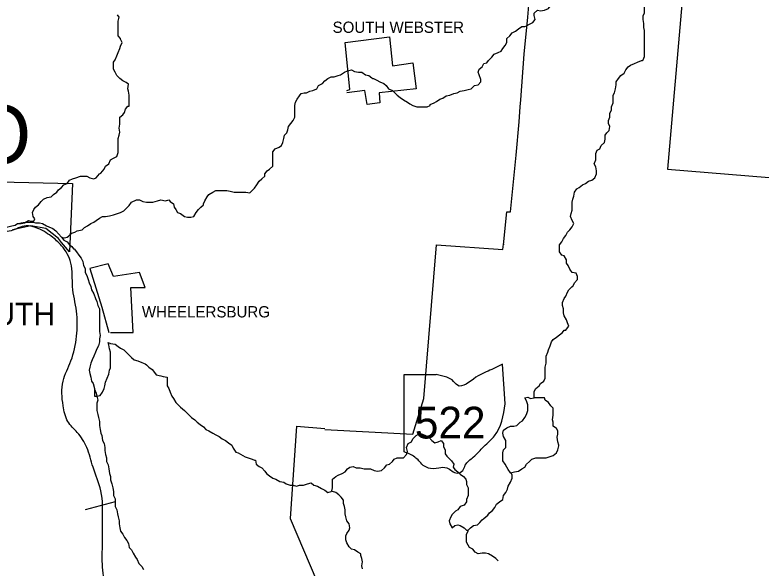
# Model space of a CAD drawing. Extents: x 0 to 34, y 0 to 22.
# Drawn here: x 6.387 to 7.678, y 15.869 to 16.826 of the extents above; entities that cross this region are included whole.
import ezdxf

# ---------------------------------------------------------------- set-up
doc = ezdxf.new("R2010")
doc.units = 0
doc.layers.add('Default', color=7, linetype='Continuous')
doc.layers.add('TR_Turning_Path1', color=7, linetype='Continuous')

msp = doc.modelspace()

# ---------------------------------------------------------------- linework, layer by layer
at = {"layer": 'Default'}
msp.add_line((7.0753, 16.1005), (7.0753, 16.1005), dxfattribs=at)
for points in [[(7.232, 16.4277), (7.2375, 16.485), (7.2443, 16.485), (7.2539, 16.5832), (7.2593, 16.6404), (7.2607, 16.6663), (7.262, 16.6786), (7.2675, 16.7577), (7.2743, 16.8218), (7.2784, 16.8777), (7.2784, 16.8777), (7.2784, 16.8777)], [(7.2716, 16.8068), (7.277, 16.8095), (7.2825, 16.8122), (7.2866, 16.8177), (7.2852, 16.8245), (7.2852, 16.8286), (7.2907, 16.834), (7.2961, 16.8327), (7.3029, 16.834), (7.3098, 16.8368), (7.3125, 16.8409), (7.3179, 16.8422), (7.3261, 16.845), (7.3316, 16.8463), (7.337, 16.8504), (7.337, 16.8572), (7.3425, 16.8613), (7.3438, 16.8681), (7.3452, 16.8695), (7.3452, 16.8709)], [(7.4734, 16.7481), (7.4761, 16.7536), (7.4761, 16.7604), (7.4761, 16.7672), (7.4761, 16.7727), (7.4761, 16.7795), (7.4761, 16.785), (7.4761, 16.7918), (7.4761, 16.7986), (7.4747, 16.804), (7.4747, 16.8109), (7.4734, 16.8177), (7.4734, 16.8245), (7.4761, 16.8286), (7.4761, 16.8368), (7.4761, 16.8422), (7.4734, 16.8463), (7.4706, 16.8531), (7.4679, 16.8586), (7.4652, 16.8613), (7.4638, 16.8613)], [(7.5415, 16.8572), (7.5156, 16.5586), (7.8674, 16.53), (7.8579, 16.3964), (7.926, 16.3909), (7.9124, 16.2178), (7.9056, 16.1223), (8.2369, 16.1019), (8.2751, 16.0978), (8.3241, 16.0951)], [(6.5694, 16.785), (6.5653, 16.7891), (6.5653, 16.7959), (6.5653, 16.8013), (6.5653, 16.8095), (6.5653, 16.815), (6.5667, 16.8218), (6.564, 16.8259)], [(7.2034, 16.7427), (7.2061, 16.7468), (7.2116, 16.7522), (7.2157, 16.7577), (7.2225, 16.7604), (7.228, 16.7631), (7.2307, 16.7672), (7.2348, 16.7727), (7.2375, 16.7781), (7.2375, 16.785), (7.243, 16.7891), (7.247, 16.7945), (7.2525, 16.7972), (7.258, 16.8013), (7.2634, 16.8054), (7.2689, 16.8054), (7.2716, 16.8068)], [(6.5844, 16.6677), (6.5844, 16.6745), (6.5844, 16.68), (6.5844, 16.6868), (6.5831, 16.6936), (6.5817, 16.6977), (6.5831, 16.7059), (6.579, 16.7086), (6.5735, 16.7113), (6.5681, 16.7154), (6.5626, 16.7209), (6.5599, 16.7263), (6.5572, 16.7318), (6.5572, 16.7372), (6.5572, 16.7441), (6.5599, 16.7481), (6.5626, 16.755), (6.5653, 16.7604), (6.5681, 16.7672), (6.5694, 16.7713), (6.5722, 16.7781), (6.5694, 16.7836), (6.5694, 16.785)], [(6.9607, 16.695), (6.9662, 16.6963), (6.958, 16.7781), (7.0344, 16.7877), (7.0398, 16.7372), (7.0753, 16.7427), (7.0807, 16.6977), (7.0166, 16.6909), (7.018, 16.6732), (6.9962, 16.6704), (6.9921, 16.695), (6.9607, 16.6909)], [(7.3984, 16.5941), (7.4011, 16.5995), (7.4066, 16.605), (7.4079, 16.6104), (7.4079, 16.6173), (7.4107, 16.6214), (7.4147, 16.6254), (7.4161, 16.6323), (7.4134, 16.6377), (7.4134, 16.6432), (7.4161, 16.6486), (7.4161, 16.6554), (7.4188, 16.6609), (7.4188, 16.6663), (7.4216, 16.6732), (7.4216, 16.68), (7.4216, 16.6868), (7.4243, 16.6909), (7.4257, 16.6977), (7.427, 16.7045), (7.427, 16.71), (7.4311, 16.7154), (7.4352, 16.7209), (7.4407, 16.725), (7.4434, 16.7304), (7.4475, 16.7359), (7.4516, 16.7386), (7.4584, 16.7413), (7.4638, 16.7441), (7.4706, 16.7468), (7.472, 16.7468), (7.4734, 16.7481)], [(7.1053, 16.6704), (7.1121, 16.6732), (7.1162, 16.6759), (7.1216, 16.68), (7.1271, 16.6813), (7.1325, 16.6854), (7.1393, 16.6868), (7.1462, 16.6895), (7.1516, 16.6909), (7.1571, 16.6936), (7.1639, 16.695), (7.1707, 16.6963), (7.1761, 16.6977), (7.1816, 16.7032), (7.1884, 16.7045), (7.1925, 16.71), (7.1925, 16.7141), (7.1898, 16.7222), (7.1884, 16.7263), (7.1898, 16.7318), (7.1952, 16.7359), (7.198, 16.7413), (7.2034, 16.7427)], [(6.8912, 16.6909), (6.8966, 16.6936), (6.9021, 16.695), (6.9089, 16.6977), (6.9116, 16.7032), (6.9185, 16.7072), (6.9226, 16.7113), (6.928, 16.7154), (6.9335, 16.7182), (6.9389, 16.7182), (6.9457, 16.7209), (6.9498, 16.7222), (6.9566, 16.7263), (6.9621, 16.7291), (6.9689, 16.7304), (6.9744, 16.7277), (6.9812, 16.7263), (6.9866, 16.7263), (6.9934, 16.7222), (6.9989, 16.7209), (7.0044, 16.7168), (7.0057, 16.7154), (7.0071, 16.7154)], [(7.0071, 16.7154), (7.0125, 16.7127), (7.018, 16.71), (7.0248, 16.7072), (7.0289, 16.7032), (7.033, 16.6977), (7.0398, 16.695), (7.0439, 16.6909), (7.048, 16.6868), (7.0534, 16.6827), (7.0589, 16.6786), (7.0657, 16.6745), (7.0698, 16.6718), (7.0753, 16.6691), (7.0821, 16.6663), (7.0889, 16.6663), (7.0943, 16.6663), (7.0998, 16.6663), (7.1053, 16.6691), (7.1053, 16.6704)], [(6.8189, 16.5505), (6.823, 16.5559), (6.8271, 16.5586), (6.8326, 16.5641), (6.8326, 16.5709), (6.8326, 16.5764), (6.8326, 16.5832), (6.8326, 16.5886), (6.8367, 16.5941), (6.8435, 16.5968), (6.8476, 16.5995), (6.8503, 16.605), (6.8517, 16.6118), (6.853, 16.6173), (6.8571, 16.6214), (6.8585, 16.6268), (6.8598, 16.6323), (6.8639, 16.6377), (6.868, 16.6432), (6.8707, 16.6486), (6.8707, 16.6568), (6.8707, 16.6623), (6.8707, 16.6691), (6.8721, 16.6745), (6.8748, 16.68), (6.8789, 16.6854), (6.8816, 16.6895), (6.8871, 16.6909), (6.8912, 16.6909)], [(6.5272, 16.5436), (6.5326, 16.5505), (6.5353, 16.5518), (6.5408, 16.5586), (6.5435, 16.5641), (6.549, 16.5682), (6.5517, 16.575), (6.5572, 16.5777), (6.5626, 16.5804), (6.5653, 16.5873), (6.5653, 16.5927), (6.5653, 16.5995), (6.5653, 16.605), (6.5653, 16.6118), (6.5667, 16.6173), (6.5681, 16.6227), (6.5667, 16.6295), (6.5681, 16.6363), (6.5681, 16.6418), (6.5681, 16.6486), (6.5735, 16.6527), (6.5762, 16.6568), (6.5776, 16.6623), (6.5817, 16.6677), (6.5844, 16.6677), (6.5844, 16.6677)], [(7.3466, 16.4537), (7.3507, 16.4591), (7.3534, 16.4646), (7.3507, 16.47), (7.3479, 16.4768), (7.3493, 16.4823), (7.3507, 16.4877), (7.3507, 16.4932), (7.3507, 16.5014), (7.352, 16.5068), (7.3534, 16.5123), (7.3548, 16.5191), (7.3588, 16.5245), (7.3629, 16.5273), (7.3684, 16.5314), (7.3738, 16.5341), (7.3793, 16.5382), (7.3848, 16.5395), (7.3902, 16.5436), (7.3929, 16.5505), (7.3929, 16.5559), (7.3916, 16.5627), (7.3888, 16.5682), (7.3916, 16.575), (7.3916, 16.5804), (7.3916, 16.5859), (7.3943, 16.5914), (7.3984, 16.5941)], [(6.2327, 16.5395), (6.4863, 16.5341), (6.4808, 16.4155), (6.4672, 16.4318), (6.4617, 16.4387), (6.4399, 16.4564), (6.414, 16.4605), (6.3826, 16.4537)], [(6.4194, 16.4686), (6.4208, 16.4727), (6.4181, 16.4768), (6.4167, 16.4836), (6.4194, 16.4891), (6.4222, 16.4932), (6.4276, 16.4973), (6.4317, 16.5027), (6.4358, 16.5068), (6.4426, 16.5096), (6.4494, 16.5109), (6.4535, 16.515), (6.459, 16.5191), (6.4617, 16.5232), (6.4672, 16.5273), (6.4713, 16.5314), (6.4767, 16.5341), (6.4808, 16.5395), (6.4863, 16.5423), (6.4917, 16.5436), (6.4999, 16.5464), (6.5053, 16.5464), (6.5108, 16.5464), (6.5163, 16.5436), (6.5231, 16.5423), (6.5272, 16.5436), (6.5272, 16.5436)], [(6.7126, 16.4986), (6.7153, 16.5041), (6.7194, 16.5109), (6.7221, 16.515), (6.7289, 16.5191), (6.7344, 16.5218), (6.7399, 16.5218), (6.7467, 16.5218), (6.7535, 16.5218), (6.7589, 16.5205), (6.7658, 16.5191), (6.7726, 16.5191), (6.7808, 16.5191), (6.7862, 16.5191), (6.793, 16.5177), (6.7971, 16.5218), (6.8012, 16.5259), (6.8053, 16.5314), (6.8094, 16.5382), (6.8135, 16.5423), (6.8189, 16.5464), (6.8189, 16.5491), (6.8189, 16.5505)], [(6.4794, 16.4427), (6.4849, 16.4482), (6.4903, 16.4496), (6.4944, 16.4523), (6.5026, 16.4537), (6.5067, 16.4577), (6.5122, 16.4605), (6.5176, 16.4646), (6.5231, 16.4673), (6.5272, 16.47), (6.5326, 16.4741), (6.5381, 16.4768), (6.5435, 16.4768), (6.5503, 16.4782), (6.5572, 16.4796), (6.564, 16.4823), (6.5694, 16.4836), (6.5749, 16.4864), (6.579, 16.4905), (6.5844, 16.4959), (6.5885, 16.5014), (6.5967, 16.5055), (6.5967, 16.5055)], [(6.5967, 16.5055), (6.6021, 16.5055), (6.6076, 16.5027), (6.6144, 16.5014), (6.6199, 16.5014), (6.6253, 16.5014), (6.6335, 16.5041), (6.639, 16.5055), (6.6471, 16.5041), (6.6526, 16.5055), (6.6553, 16.5027), (6.6608, 16.4986), (6.6621, 16.4932), (6.6649, 16.4891), (6.6676, 16.4836), (6.673, 16.4823), (6.6799, 16.4768), (6.6853, 16.4755), (6.6908, 16.4755), (6.6962, 16.4768), (6.7003, 16.4836), (6.7044, 16.4891), (6.7085, 16.4932), (6.7126, 16.4973), (6.7126, 16.4973), (6.7126, 16.4986)], [(6.3036, 16.4523), (6.309, 16.4523), (6.3158, 16.4523), (6.3226, 16.4537), (6.3295, 16.4537), (6.3363, 16.4537), (6.3417, 16.4564), (6.3472, 16.4564), (6.3554, 16.4577), (6.3608, 16.4577), (6.3676, 16.4577), (6.3745, 16.4591), (6.3813, 16.4605), (6.3867, 16.4618), (6.3908, 16.4646), (6.3922, 16.4646)], [(6.3922, 16.4646), (6.3976, 16.4646), (6.4031, 16.4659), (6.4099, 16.47), (6.4154, 16.4686), (6.4194, 16.4686)], [(6.3922, 16.4646), (6.3976, 16.4659), (6.4045, 16.4673), (6.4099, 16.4673), (6.4181, 16.4673), (6.4222, 16.4659), (6.429, 16.4659), (6.4344, 16.4646), (6.4413, 16.4605), (6.4454, 16.4591), (6.4522, 16.4564), (6.4576, 16.4523), (6.4617, 16.4468), (6.4672, 16.4414), (6.4672, 16.4414)], [(7.352, 16.3555), (7.3548, 16.3623), (7.3602, 16.3678), (7.3602, 16.3732), (7.3575, 16.3787), (7.3507, 16.38), (7.3466, 16.3855), (7.3438, 16.3923), (7.3411, 16.3964), (7.3411, 16.4018), (7.337, 16.4087), (7.3329, 16.41), (7.3289, 16.4155), (7.3289, 16.4209), (7.3289, 16.4277), (7.3329, 16.4332), (7.3357, 16.4387), (7.3398, 16.4441), (7.3425, 16.4496), (7.3452, 16.4523), (7.3466, 16.4537)], [(6.4672, 16.4414), (6.4726, 16.44), (6.4767, 16.4414), (6.4794, 16.4427)], [(6.4672, 16.4414), (6.4713, 16.4359), (6.4767, 16.4332), (6.4808, 16.4277), (6.4849, 16.425), (6.4876, 16.4209), (6.489, 16.4209)], [(7.0943, 16.1619), (7.1162, 16.4277)], [(7.1162, 16.4277), (7.2307, 16.4196)], [(7.2307, 16.4196), (7.232, 16.4291), (7.232, 16.4277)], [(6.489, 16.4209), (6.4931, 16.4155), (6.4972, 16.41), (6.5013, 16.4046), (6.504, 16.3991), (6.5053, 16.3923), (6.5081, 16.3868), (6.5081, 16.38), (6.5108, 16.3746), (6.5135, 16.3678), (6.5149, 16.3623), (6.5176, 16.3555), (6.519, 16.35), (6.5231, 16.3432), (6.5258, 16.335)], [(6.5517, 16.2764), (6.5912, 16.2764), (6.5872, 16.3541), (6.6117, 16.3541), (6.6021, 16.38), (6.5572, 16.3732), (6.5476, 16.395), (6.5163, 16.3868), (6.5367, 16.32), (6.549, 16.2764)], [(7.3411, 16.2819), (7.3452, 16.2873), (7.3425, 16.2928), (7.3411, 16.2982), (7.337, 16.305), (7.3357, 16.3105), (7.3357, 16.3173), (7.3343, 16.3228), (7.3343, 16.3282), (7.337, 16.335), (7.3398, 16.3391), (7.3425, 16.3459), (7.3452, 16.35), (7.3507, 16.3555), (7.352, 16.3555)], [(6.5258, 16.335), (6.5285, 16.3296), (6.5299, 16.3228), (6.5326, 16.3173), (6.5326, 16.3105), (6.5326, 16.305), (6.5326, 16.2982), (6.5326, 16.2914), (6.5326, 16.2859), (6.5326, 16.2778), (6.534, 16.271), (6.5326, 16.2655), (6.5326, 16.26), (6.5313, 16.2532), (6.5285, 16.2478), (6.5258, 16.2423), (6.5231, 16.2355), (6.5203, 16.2287), (6.5176, 16.2232), (6.5163, 16.2164), (6.5149, 16.211), (6.5163, 16.2055), (6.5176, 16.1987), (6.519, 16.1919), (6.5217, 16.1878), (6.5244, 16.1796), (6.5244, 16.1796), (6.5244, 16.1782)], [(7.2852, 16.1632), (7.2852, 16.1701), (7.2852, 16.1741), (7.2879, 16.1796), (7.2934, 16.1837), (7.2961, 16.1878), (7.3016, 16.1919), (7.3043, 16.1973), (7.3043, 16.2041), (7.3043, 16.211), (7.3043, 16.2164), (7.3057, 16.2232), (7.3057, 16.2287), (7.3057, 16.2355), (7.3084, 16.2423), (7.3098, 16.2464), (7.3125, 16.2532), (7.3152, 16.26), (7.3179, 16.2641), (7.3234, 16.2682), (7.3289, 16.2723), (7.3343, 16.2764), (7.337, 16.2805), (7.3398, 16.2805), (7.3411, 16.2819)], [(6.5244, 16.1782), (6.5244, 16.1714), (6.5244, 16.166), (6.5285, 16.166), (6.534, 16.1673), (6.5381, 16.1728), (6.5408, 16.1796), (6.5422, 16.1837), (6.5435, 16.1905), (6.5462, 16.1973), (6.549, 16.2041), (6.5503, 16.211), (6.5517, 16.2151), (6.5517, 16.2219), (6.5517, 16.2287), (6.5517, 16.2355), (6.5517, 16.2423), (6.5503, 16.2478), (6.549, 16.2546), (6.5476, 16.2587)], [(6.5476, 16.2587), (6.5517, 16.2573), (6.5599, 16.256), (6.5653, 16.2519), (6.5694, 16.2491), (6.5749, 16.2464), (6.579, 16.2423), (6.5844, 16.2369), (6.5885, 16.2328), (6.5926, 16.2287), (6.5994, 16.2273), (6.6062, 16.2246), (6.6117, 16.2219), (6.6144, 16.2205)], [(6.6144, 16.2205), (6.6185, 16.2164), (6.624, 16.2123), (6.6281, 16.2069), (6.6308, 16.2028), (6.639, 16.2014), (6.6431, 16.2001), (6.6499, 16.1987), (6.6499, 16.1905), (6.6499, 16.1837), (6.6526, 16.1796), (6.6553, 16.1728), (6.658, 16.166), (6.6608, 16.1619), (6.6649, 16.1551), (6.669, 16.151), (6.673, 16.1469), (6.6799, 16.1414), (6.6826, 16.1387), (6.688, 16.1332), (6.6921, 16.1292), (6.6976, 16.1251), (6.6976, 16.1251)], [(7.2349, 16.1527), (7.2303, 16.2217)], [(7.0601, 16.0698), (7.0601, 16.2033), (7.1153, 16.2033)], [(6.5244, 16.1782), (6.5272, 16.1714), (6.5285, 16.166), (6.5299, 16.1592), (6.5285, 16.1537), (6.5285, 16.1469), (6.5285, 16.1414), (6.5299, 16.1346), (6.5313, 16.1292), (6.5326, 16.1223), (6.5326, 16.1155), (6.534, 16.1087), (6.5353, 16.1019), (6.5367, 16.0978), (6.5381, 16.0896), (6.5408, 16.0842), (6.5422, 16.0773), (6.5422, 16.0719), (6.5435, 16.0651), (6.5449, 16.0596), (6.5449, 16.0528), (6.5476, 16.0474), (6.549, 16.0405), (6.5503, 16.0324), (6.5517, 16.0269), (6.5517, 16.0214), (6.5544, 16.0146), (6.5558, 16.0078), (6.5572, 16.001), (6.5572, 15.9942), (6.5599, 15.9887), (6.5599, 15.9833), (6.5599, 15.9751), (6.5626, 15.9696), (6.564, 15.9628), (6.5653, 15.9574), (6.5667, 15.9505), (6.5667, 15.9451), (6.5681, 15.9383), (6.5694, 15.9328), (6.5735, 15.9274)], [(7.0753, 16.1005), (7.0943, 16.1619), (7.0943, 16.1619)], [(7.2443, 16.0337), (7.2402, 16.0392), (7.2375, 16.0433), (7.2348, 16.0487), (7.2307, 16.0542), (7.2307, 16.0596), (7.2307, 16.0678), (7.232, 16.0733), (7.2361, 16.0773), (7.2361, 16.0842), (7.2361, 16.0896), (7.232, 16.0964), (7.2307, 16.1019), (7.232, 16.1073), (7.2375, 16.1114), (7.2443, 16.1142), (7.2498, 16.1142), (7.2552, 16.1155), (7.2607, 16.121), (7.2648, 16.1237), (7.2689, 16.1292), (7.2716, 16.1346), (7.2743, 16.1414), (7.2743, 16.1469), (7.2743, 16.151), (7.2716, 16.1578), (7.2689, 16.1632), (7.2743, 16.1646), (7.2784, 16.1619), (7.2852, 16.1632), (7.2852, 16.1632)], [(7.3275, 16.0814), (7.3261, 16.0869), (7.3248, 16.0951), (7.3261, 16.1005), (7.3261, 16.106), (7.3234, 16.1101), (7.3179, 16.1142), (7.3179, 16.121), (7.3166, 16.1251), (7.3179, 16.1332), (7.3179, 16.1387), (7.3179, 16.1455), (7.3139, 16.1496), (7.3098, 16.1551), (7.3043, 16.1592), (7.3029, 16.1632), (7.2975, 16.1632), (7.2934, 16.1632), (7.2866, 16.1632), (7.2852, 16.1632), (7.2852, 16.1632)], [(6.8735, 16.1142), (6.8626, 15.9546), (6.9553, 15.7379), (6.6853, 15.6179)], [(6.6976, 16.1251), (6.7017, 16.121), (6.7071, 16.1169), (6.7126, 16.1128), (6.7167, 16.1087), (6.7221, 16.106), (6.7289, 16.1019), (6.7344, 16.0992), (6.7399, 16.0964), (6.7453, 16.0923), (6.7508, 16.0896), (6.7562, 16.0855), (6.7617, 16.0814), (6.7644, 16.076), (6.7685, 16.0692), (6.7726, 16.0678), (6.7808, 16.0637), (6.7848, 16.061), (6.7903, 16.0596), (6.7971, 16.0569), (6.8012, 16.0555), (6.8026, 16.0555)], [(6.8735, 16.1142), (6.9226, 16.1101), (6.9226, 16.1101)], [(6.9226, 16.1087), (7.0753, 16.1005)], [(7.0807, 16.0978), (7.0848, 16.1005), (7.0916, 16.1005), (7.0971, 16.0978), (7.1025, 16.0951), (7.108, 16.0896), (7.1134, 16.0855), (7.1189, 16.0869), (7.1243, 16.0896), (7.1284, 16.0842), (7.1284, 16.0787), (7.1312, 16.0733), (7.1312, 16.0664), (7.1339, 16.0623), (7.138, 16.0583), (7.1421, 16.0542), (7.1462, 16.0487), (7.1448, 16.0433), (7.1475, 16.0392), (7.153, 16.0351), (7.1571, 16.031), (7.1625, 16.0269), (7.1666, 16.0228), (7.168, 16.0187), (7.168, 16.0187)], [(7.0016, 16.0405), (7.0084, 16.0378), (7.0139, 16.0364), (7.0207, 16.0378), (7.0262, 16.0419), (7.0303, 16.0474), (7.0344, 16.0487), (7.0398, 16.0528), (7.0425, 16.0569), (7.048, 16.0596), (7.0534, 16.0596), (7.0589, 16.0596), (7.0643, 16.0651), (7.0657, 16.0705), (7.0643, 16.0773), (7.0671, 16.0842), (7.0725, 16.0869), (7.0753, 16.0923), (7.0807, 16.0978), (7.0807, 16.0978), (7.0807, 16.0978)], [(7.2443, 16.0337), (7.2511, 16.0351), (7.258, 16.0364), (7.2634, 16.0405), (7.2689, 16.0433), (7.2716, 16.0487), (7.277, 16.0528), (7.2811, 16.0569), (7.2879, 16.0596), (7.2934, 16.0596), (7.3002, 16.0596), (7.3057, 16.0596), (7.3111, 16.061), (7.3179, 16.0637), (7.3234, 16.0678), (7.3261, 16.0733), (7.3275, 16.0801), (7.3275, 16.0814)], [(6.8026, 16.0555), (6.8039, 16.0487), (6.8094, 16.0446), (6.8135, 16.0419), (6.8189, 16.0364), (6.8217, 16.0324), (6.8271, 16.0283), (6.8326, 16.0242), (6.838, 16.0228), (6.8448, 16.0187), (6.8517, 16.0174), (6.8557, 16.0146), (6.8626, 16.0119), (6.868, 16.0119)], [(6.9348, 16.0024), (6.9362, 16.0078), (6.9362, 16.0146), (6.9362, 16.0228), (6.9416, 16.0269), (6.9457, 16.0296), (6.9525, 16.0324), (6.958, 16.0351), (6.9621, 16.0405), (6.9662, 16.0433), (6.9716, 16.0446), (6.9771, 16.0419), (6.9839, 16.0419), (6.9907, 16.0405), (6.9975, 16.0405), (7.0003, 16.0405), (7.0016, 16.0405)], [(7.1707, 15.9342), (7.1748, 15.9383), (7.1802, 15.9424), (7.1871, 15.9437), (7.1911, 15.9478), (7.1952, 15.9519), (7.198, 15.9546), (7.2048, 15.9601), (7.2075, 15.9642), (7.213, 15.9683), (7.2171, 15.9737), (7.2198, 15.9792), (7.2252, 15.9833), (7.2307, 15.9874), (7.232, 15.9942), (7.2361, 15.9996), (7.2389, 16.0051), (7.2402, 16.0105), (7.2443, 16.0174), (7.247, 16.0242), (7.247, 16.0296), (7.2457, 16.0324), (7.2443, 16.0337)], [(6.868, 16.0119), (6.8735, 16.0105), (6.8789, 16.0119), (6.8857, 16.0119), (6.8926, 16.0146), (6.8994, 16.016), (6.9035, 16.0119), (6.9103, 16.0105), (6.9171, 16.0064), (6.9226, 16.0037), (6.928, 15.9996), (6.9335, 16.001), (6.9348, 16.0024)], [(7.168, 16.0187), (7.168, 16.0133), (7.1707, 16.0078), (7.1707, 15.9996), (7.1707, 15.9942), (7.168, 15.9874), (7.168, 15.9833), (7.1639, 15.9778), (7.1571, 15.9751), (7.153, 15.9696), (7.1489, 15.9669), (7.1434, 15.9615), (7.1407, 15.9574), (7.138, 15.9505), (7.1393, 15.9451), (7.1434, 15.9383), (7.1475, 15.9424), (7.153, 15.9437), (7.1571, 15.9424), (7.1639, 15.9383), (7.168, 15.9342), (7.1707, 15.9342)], [(6.9853, 15.8933), (6.9798, 15.896), (6.9744, 15.9001), (6.9689, 15.9015), (6.9648, 15.9056), (6.9607, 15.9124), (6.9594, 15.9178), (6.9594, 15.9246), (6.9607, 15.9287), (6.9648, 15.9342), (6.9662, 15.9383), (6.9648, 15.9451), (6.9607, 15.9505), (6.9594, 15.9574), (6.958, 15.9628), (6.958, 15.9696), (6.9566, 15.9751), (6.9553, 15.9805), (6.9553, 15.986), (6.9512, 15.9915), (6.9471, 15.9955), (6.9416, 15.9996), (6.9362, 16.001), (6.9348, 16.0024)], [(6.5599, 15.9833), (6.5081, 15.9696)], [(7.2225, 15.881), (7.2184, 15.8851), (7.213, 15.8892), (7.2061, 15.8933), (7.2007, 15.8946), (7.1952, 15.8946), (7.1884, 15.8933), (7.183, 15.896), (7.1789, 15.9015), (7.1734, 15.9042), (7.1707, 15.9083), (7.168, 15.9137), (7.168, 15.9206), (7.168, 15.9274), (7.1707, 15.9328), (7.1707, 15.9342)], [(6.5735, 15.9274), (6.5762, 15.9219), (6.5803, 15.9165), (6.5831, 15.911), (6.5844, 15.9042), (6.5885, 15.9001), (6.5912, 15.8946), (6.5953, 15.8878), (6.5981, 15.8837), (6.6008, 15.8769), (6.6062, 15.8715), (6.609, 15.866)], [(6.988, 15.8674), (6.9866, 15.8728), (6.988, 15.8797), (6.9866, 15.8851), (6.9853, 15.8906), (6.9853, 15.8933)]]:
    msp.add_lwpolyline(points, dxfattribs=at)
for points in [[(6.6853, 15.6179), (6.6553, 15.637), (6.6308, 15.656), (6.5994, 15.6806), (6.579, 15.7174), (6.5653, 15.7529), (6.5531, 15.7842), (6.5435, 15.8306), (6.5381, 15.8701), (6.5381, 15.9124), (6.5381, 15.9505), (6.5353, 16.0024), (6.5217, 16.0433), (6.5108, 16.0773), (6.4944, 16.1033), (6.4781, 16.1223), (6.4699, 16.1496), (6.4699, 16.1919), (6.4835, 16.2273), (6.4931, 16.2696), (6.4931, 16.3132), (6.4863, 16.3555), (6.4835, 16.3964), (6.4672, 16.4264), (6.4494, 16.4427), (6.4222, 16.4577), (6.4058, 16.4605), (6.3799, 16.4523), (6.3663, 16.4496), (6.3308, 16.44), (6.294, 16.4318), (6.2599, 16.4155), (6.2327, 16.3964), (6.2068, 16.38), (6.1754, 16.3623), (6.1495, 16.3473), (6.1304, 16.3364), (6.1072, 16.3282), (6.0718, 16.3296), (6.0377, 16.3364), (6.0036, 16.3391), (5.9654, 16.3459), (5.9395, 16.3282), (5.9163, 16.3105), (5.8973, 16.2696), (5.8795, 16.245), (5.8564, 16.2096), (5.8373, 16.1755), (5.8141, 16.166), (5.7746, 16.1496), (5.7418, 16.1332), (5.7009, 16.121), (5.6737, 16.106), (5.6368, 16.0896), (5.615, 16.0596), (5.6028, 16.0351), (5.5891, 15.9996), (5.5796, 15.9655), (5.5769, 15.9246), (5.5455, 15.896), (5.5114, 15.8701), (5.4637, 15.8469), (5.4132, 15.8469), (5.3723, 15.8387), (5.3273, 15.8387), (5.2837, 15.8442), (5.2428, 15.8633), (5.2169, 15.881), (5.1828, 15.8878), (5.1569, 15.8892), (5.1392, 15.8728), (5.1051, 15.8619), (5.0819, 15.8442)], [(7.2303, 16.2217), (7.2119, 16.2125), (7.1843, 16.1987), (7.1521, 16.1849), (7.1429, 16.1941), (7.1337, 16.1987), (7.1153, 16.2033)], [(7.0923, 16.0468), (7.1015, 16.0422), (7.1199, 16.0422), (7.1337, 16.0422), (7.1521, 16.033), (7.1613, 16.0376), (7.1659, 16.0468), (7.1797, 16.0606), (7.1981, 16.0791), (7.2165, 16.0975), (7.2349, 16.1527)], [(7.0923, 16.0468), (7.0785, 16.0606), (7.0601, 16.0698)]]:
    msp.add_spline(points, degree=3, dxfattribs=at)

# ---------------------------------------------------------------- texts
for s, height, p in [('SOUTH WEBSTER', 0.019502, (6.9362, 16.7945)), ('PORTSMOUTH', 0.039, (6.0854, 16.2887)), ('WHEELERSBURG', 0.019502, (6.6062, 16.3023)), ('522', 0.05486, (7.0785, 16.0929))]:
    msp.add_text(s, height=height, dxfattribs=at).set_placement(p)
at = {"layer": 'TR_Turning_Path1'}
msp.add_text('S   C   I   O   T   O', height=0.101489, dxfattribs=at).set_placement((5.3287, 16.5682))

doc.saveas('drawing.dxf')
